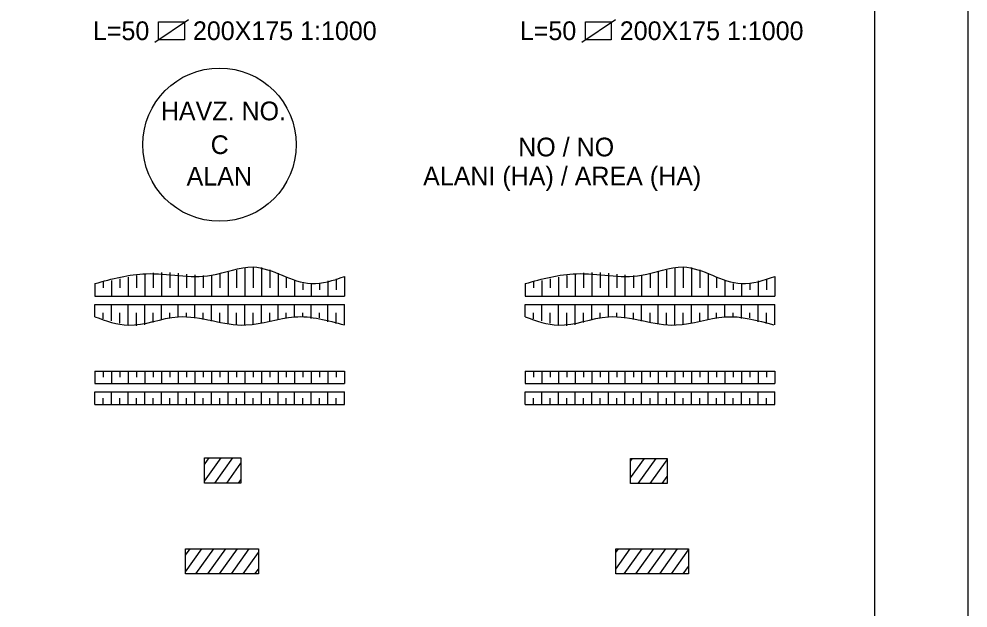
# Model space of a CAD drawing. Extents: x -10 to 1145, y -10 to 821.
# Drawn here: x 1043 to 1145, y 552.8 to 616.2 of the extents above; entities that cross this region are included whole.
import ezdxf

# ---------------------------------------------------------------- set-up
doc = ezdxf.new("R2010")
doc.units = 0
for name, color, linetype in [('Level 1', 7, 'Continuous'), ('Level 17', 7, 'Continuous'), ('Level 19', 7, 'Continuous'), ('Level 31', 7, 'Continuous'), ('Level 32', 7, 'Continuous'), ('Level 39', 7, 'Continuous'), ('Level 51', 7, 'Continuous'), ('Level 52', 7, 'Continuous')]:
    doc.layers.add(name, color=color, linetype=linetype)

msp = doc.modelspace()

# ---------------------------------------------------------------- linework, layer by layer
at = {"layer": 'Level 1'}
for p, q in [((1055.63, 588.62), (1055.63, 587.31)), ((1056.52, 588.79), (1056.52, 586.41)), ((1057.42, 588.92), (1057.42, 587.31)), ((1058.31, 588.96), (1058.31, 586.41)), ((1059.21, 588.93), (1059.21, 587.31)), ((1060.1, 588.87), (1060.1, 586.41)), ((1061, 588.78), (1061, 587.31)), ((1061.89, 588.7), (1061.89, 586.41)), ((1062.79, 588.64), (1062.79, 587.31)), ((1063.68, 588.65), (1063.68, 586.41)), ((1064.57, 588.76), (1064.57, 587.31)), ((1065.47, 588.98), (1065.47, 586.41)), ((1066.36, 589.21), (1066.36, 587.31)), ((1067.26, 589.43), (1067.26, 586.41)), ((1068.15, 589.54), (1068.15, 587.31)), ((1069.05, 589.47), (1069.05, 586.41)), ((1069.94, 589.23), (1069.94, 587.31)), ((1070.84, 588.87), (1070.84, 586.41)), ((1101.87, 588.62), (1101.87, 587.31)), ((1102.77, 588.79), (1102.77, 586.41)), ((1103.66, 588.92), (1103.66, 587.31)), ((1104.55, 588.96), (1104.55, 586.41)), ((1105.45, 588.93), (1105.45, 587.31)), ((1106.34, 588.87), (1106.34, 586.41)), ((1107.24, 588.78), (1107.24, 587.31)), ((1108.13, 588.7), (1108.13, 586.41)), ((1109.03, 588.64), (1109.03, 587.31)), ((1109.92, 588.65), (1109.92, 586.41)), ((1110.82, 588.76), (1110.82, 587.31)), ((1111.71, 588.98), (1111.71, 586.41)), ((1112.6, 589.21), (1112.6, 587.31)), ((1113.5, 589.43), (1113.5, 586.41)), ((1114.39, 589.54), (1114.39, 587.31)), ((1115.29, 589.47), (1115.29, 586.41)), ((1116.18, 589.23), (1116.18, 587.31)), ((1117.08, 588.87), (1117.08, 586.41)), ((1051.16, 587.75), (1051.16, 586.41)), ((1052.05, 587.93), (1052.05, 587.31)), ((1052.95, 588.1), (1052.95, 586.41)), ((1053.84, 588.27), (1053.84, 587.31)), ((1054.74, 588.44), (1054.74, 586.41)), ((1071.73, 588.49), (1071.73, 587.31)), ((1072.62, 588.12), (1072.62, 586.41)), ((1073.52, 587.75), (1073.52, 587.08)), ((1074.41, 587.75), (1074.41, 586.41)), ((1075.31, 587.75), (1075.31, 587.08)), ((1076.2, 588.04), (1076.2, 586.41)), ((1077.1, 588.28), (1077.1, 587.08)), ((1077.99, 588.51), (1077.99, 586.41)), ((1097.4, 587.75), (1097.4, 586.41)), ((1098.29, 587.93), (1098.29, 587.31)), ((1099.19, 588.1), (1099.19, 586.41)), ((1100.08, 588.27), (1100.08, 587.31)), ((1100.98, 588.44), (1100.98, 586.41)), ((1117.97, 588.49), (1117.97, 587.31)), ((1118.86, 588.12), (1118.86, 586.41)), ((1119.76, 587.75), (1119.76, 587.08)), ((1120.65, 587.75), (1120.65, 586.41)), ((1121.55, 587.75), (1121.55, 587.08)), ((1122.44, 588.04), (1122.44, 586.41)), ((1123.34, 588.28), (1123.34, 587.08)), ((1124.23, 588.51), (1124.23, 586.41)), ((1051.16, 586.41), (1077.99, 586.41)), ((1051.16, 585.52), (1077.99, 585.52)), ((1051.16, 584.18), (1051.16, 585.52)), ((1052.95, 583.73), (1052.95, 585.52)), ((1054.74, 583.28), (1054.74, 585.52)), ((1056.52, 583.33), (1056.52, 585.52)), ((1058.31, 583.85), (1058.31, 585.52)), ((1060.1, 584.18), (1060.1, 585.52)), ((1061.89, 584.03), (1061.89, 585.52)), ((1063.68, 583.72), (1063.68, 585.52)), ((1065.47, 583.43), (1065.47, 585.52)), ((1067.26, 583.3), (1067.26, 585.52)), ((1069.05, 583.53), (1069.05, 585.52)), ((1070.84, 583.93), (1070.84, 585.52)), ((1072.62, 584.18), (1072.62, 585.52)), ((1074.41, 584.01), (1074.41, 585.52)), ((1076.2, 583.64), (1076.2, 585.52)), ((1077.99, 583.31), (1077.99, 585.52)), ((1097.4, 586.41), (1124.23, 586.41)), ((1097.4, 585.52), (1124.23, 585.52)), ((1097.4, 584.18), (1097.4, 585.52)), ((1099.19, 583.73), (1099.19, 585.52)), ((1100.98, 583.28), (1100.98, 585.52)), ((1102.77, 583.33), (1102.77, 585.52)), ((1104.55, 583.85), (1104.55, 585.52)), ((1106.34, 584.18), (1106.34, 585.52)), ((1108.13, 584.03), (1108.13, 585.52)), ((1109.92, 583.72), (1109.92, 585.52)), ((1111.71, 583.43), (1111.71, 585.52)), ((1113.5, 583.3), (1113.5, 585.52)), ((1115.29, 583.53), (1115.29, 585.52)), ((1117.08, 583.93), (1117.08, 585.52)), ((1118.86, 584.18), (1118.86, 585.52)), ((1120.65, 584.01), (1120.65, 585.52)), ((1122.44, 583.64), (1122.44, 585.52)), ((1124.23, 583.31), (1124.23, 585.52)), ((1052.05, 583.95), (1052.05, 584.62)), ((1053.84, 583.5), (1053.84, 584.62)), ((1055.63, 583.2), (1055.63, 584.62)), ((1057.42, 583.57), (1057.42, 584.62)), ((1059.21, 584.08), (1059.21, 584.62)), ((1061, 584.18), (1061, 584.62)), ((1062.79, 583.88), (1062.79, 584.62)), ((1064.57, 583.57), (1064.57, 584.62)), ((1066.36, 583.33), (1066.36, 584.62)), ((1068.15, 583.36), (1068.15, 584.62)), ((1069.94, 583.73), (1069.94, 584.62)), ((1071.73, 583.99), (1071.73, 584.62)), ((1073.52, 584.14), (1073.52, 584.62)), ((1075.31, 584.06), (1075.31, 584.62)), ((1077.1, 583.45), (1077.1, 584.62)), ((1098.29, 583.95), (1098.29, 584.62)), ((1100.08, 583.51), (1100.08, 584.62)), ((1101.87, 583.2), (1101.87, 584.62)), ((1103.66, 583.57), (1103.66, 584.62)), ((1105.45, 584.08), (1105.45, 584.62)), ((1107.24, 584.18), (1107.24, 584.62)), ((1109.03, 583.88), (1109.03, 584.62)), ((1110.82, 583.57), (1110.82, 584.62)), ((1112.6, 583.33), (1112.6, 584.62)), ((1114.39, 583.36), (1114.39, 584.62)), ((1116.18, 583.73), (1116.18, 584.62)), ((1117.97, 583.99), (1117.97, 584.62)), ((1119.76, 584.14), (1119.76, 584.62)), ((1121.55, 584.06), (1121.55, 584.62)), ((1123.34, 583.45), (1123.34, 584.62)), ((1051.16, 578.34), (1077.99, 578.34)), ((1051.16, 578.34), (1051.16, 577)), ((1052.05, 578.34), (1052.05, 577.67)), ((1052.95, 578.34), (1052.95, 577)), ((1053.84, 578.34), (1053.84, 577.67)), ((1054.74, 578.34), (1054.74, 577)), ((1055.63, 578.34), (1055.63, 577.67)), ((1056.52, 578.34), (1056.52, 577)), ((1057.42, 578.34), (1057.42, 577.67)), ((1058.31, 578.34), (1058.31, 577)), ((1059.21, 578.34), (1059.21, 577.67)), ((1060.1, 578.34), (1060.1, 577)), ((1061, 578.34), (1061, 577.67)), ((1061.89, 578.34), (1061.89, 577)), ((1062.79, 578.34), (1062.79, 577.67)), ((1063.68, 578.34), (1063.68, 577)), ((1064.57, 578.34), (1064.57, 577.67)), ((1065.47, 578.34), (1065.47, 577)), ((1066.36, 578.34), (1066.36, 577.67)), ((1067.26, 578.34), (1067.26, 577)), ((1068.15, 578.34), (1068.15, 577.67)), ((1069.05, 578.34), (1069.05, 577)), ((1069.94, 578.34), (1069.94, 577.67)), ((1070.84, 578.34), (1070.84, 577)), ((1071.73, 578.34), (1071.73, 577.67)), ((1072.62, 578.34), (1072.62, 577)), ((1073.52, 578.34), (1073.52, 577.67)), ((1074.41, 578.34), (1074.41, 577)), ((1075.31, 578.34), (1075.31, 577.67)), ((1076.2, 578.34), (1076.2, 577)), ((1077.1, 578.34), (1077.1, 577.67)), ((1077.99, 578.34), (1077.99, 577)), ((1097.4, 578.34), (1124.23, 578.34)), ((1097.4, 578.34), (1097.4, 577)), ((1098.29, 578.34), (1098.29, 577.67)), ((1099.19, 578.34), (1099.19, 577)), ((1100.08, 578.34), (1100.08, 577.67)), ((1100.98, 578.34), (1100.98, 577)), ((1101.87, 578.34), (1101.87, 577.67)), ((1102.77, 578.34), (1102.77, 577)), ((1103.66, 578.34), (1103.66, 577.67)), ((1104.55, 578.34), (1104.55, 577)), ((1105.45, 578.34), (1105.45, 577.67)), ((1106.34, 578.34), (1106.34, 577)), ((1107.24, 578.34), (1107.24, 577.67)), ((1108.13, 578.34), (1108.13, 577)), ((1109.03, 578.34), (1109.03, 577.67)), ((1109.92, 578.34), (1109.92, 577)), ((1110.82, 578.34), (1110.82, 577.67)), ((1111.71, 578.34), (1111.71, 577)), ((1112.6, 578.34), (1112.6, 577.67)), ((1113.5, 578.34), (1113.5, 577)), ((1114.39, 578.34), (1114.39, 577.67)), ((1115.29, 578.34), (1115.29, 577)), ((1116.18, 578.34), (1116.18, 577.67)), ((1117.08, 578.34), (1117.08, 577)), ((1117.97, 578.34), (1117.97, 577.67)), ((1118.86, 578.34), (1118.86, 577)), ((1119.76, 578.34), (1119.76, 577.67)), ((1120.65, 578.34), (1120.65, 577)), ((1121.55, 578.34), (1121.55, 577.67)), ((1122.44, 578.34), (1122.44, 577)), ((1123.34, 578.34), (1123.34, 577.67)), ((1124.23, 578.34), (1124.23, 577)), ((1051.16, 577), (1077.99, 577)), ((1097.4, 577), (1124.23, 577)), ((1051.16, 576.1), (1077.99, 576.1)), ((1051.16, 574.76), (1051.16, 576.1)), ((1052.05, 574.76), (1052.05, 575.43)), ((1052.95, 574.76), (1052.95, 576.1)), ((1053.84, 574.76), (1053.84, 575.43)), ((1054.74, 574.76), (1054.74, 576.1)), ((1055.63, 574.76), (1055.63, 575.43)), ((1056.52, 574.76), (1056.52, 576.1)), ((1057.42, 574.76), (1057.42, 575.43)), ((1058.31, 574.76), (1058.31, 576.1)), ((1059.21, 574.76), (1059.21, 575.43)), ((1060.1, 574.76), (1060.1, 576.1)), ((1061, 574.76), (1061, 575.43)), ((1061.89, 574.76), (1061.89, 576.1)), ((1062.79, 574.76), (1062.79, 575.43)), ((1063.68, 574.76), (1063.68, 576.1)), ((1064.57, 574.76), (1064.57, 575.43)), ((1065.47, 574.76), (1065.47, 576.1)), ((1066.36, 574.76), (1066.36, 575.43)), ((1067.26, 574.76), (1067.26, 576.1)), ((1068.15, 574.76), (1068.15, 575.43)), ((1069.05, 574.76), (1069.05, 576.1)), ((1069.94, 574.76), (1069.94, 575.43)), ((1070.84, 574.76), (1070.84, 576.1)), ((1071.73, 574.76), (1071.73, 575.43)), ((1072.62, 574.76), (1072.62, 576.1)), ((1073.52, 574.76), (1073.52, 575.43)), ((1074.41, 574.76), (1074.41, 576.1)), ((1075.31, 574.76), (1075.31, 575.43)), ((1076.2, 574.76), (1076.2, 576.1)), ((1077.1, 574.76), (1077.1, 575.43)), ((1077.99, 574.76), (1077.99, 576.1)), ((1097.4, 576.1), (1124.23, 576.1)), ((1097.4, 574.76), (1097.4, 576.1)), ((1098.29, 574.76), (1098.29, 575.43)), ((1099.19, 574.76), (1099.19, 576.1)), ((1100.08, 574.76), (1100.08, 575.43)), ((1100.98, 574.76), (1100.98, 576.1)), ((1101.87, 574.76), (1101.87, 575.43)), ((1102.77, 574.76), (1102.77, 576.1)), ((1103.66, 574.76), (1103.66, 575.43)), ((1104.55, 574.76), (1104.55, 576.1)), ((1105.45, 574.76), (1105.45, 575.43)), ((1106.34, 574.76), (1106.34, 576.1)), ((1107.24, 574.76), (1107.24, 575.43)), ((1108.13, 574.76), (1108.13, 576.1)), ((1109.03, 574.76), (1109.03, 575.43)), ((1109.92, 574.76), (1109.92, 576.1)), ((1110.82, 574.76), (1110.82, 575.43)), ((1111.71, 574.76), (1111.71, 576.1)), ((1112.6, 574.76), (1112.6, 575.43)), ((1113.5, 574.76), (1113.5, 576.1)), ((1114.39, 574.76), (1114.39, 575.43)), ((1115.29, 574.76), (1115.29, 576.1)), ((1116.18, 574.76), (1116.18, 575.43)), ((1117.08, 574.76), (1117.08, 576.1)), ((1117.97, 574.76), (1117.97, 575.43)), ((1118.86, 574.76), (1118.86, 576.1)), ((1119.76, 574.76), (1119.76, 575.43)), ((1120.65, 574.76), (1120.65, 576.1)), ((1121.55, 574.76), (1121.55, 575.43)), ((1122.44, 574.76), (1122.44, 576.1)), ((1123.34, 574.76), (1123.34, 575.43)), ((1124.23, 574.76), (1124.23, 576.1)), ((1051.16, 574.76), (1077.99, 574.76)), ((1097.4, 574.76), (1124.23, 574.76))]:
    msp.add_line(p, q, dxfattribs=at)
for points in [[(1051.16, 587.75), (1056.67, 588.82), (1063.68, 588.65), (1068.15, 589.54), (1074.41, 587.75), (1077.97, 588.51)], [(1097.4, 587.75), (1102.91, 588.82), (1109.92, 588.65), (1114.39, 589.54), (1120.65, 587.75), (1124.23, 588.52)], [(1051.16, 584.18), (1054.74, 583.28), (1060.1, 584.18), (1067.39, 583.3), (1072.62, 584.18), (1077.97, 583.3)], [(1097.4, 584.18), (1100.98, 583.28), (1106.34, 584.18), (1113.63, 583.3), (1118.86, 584.18), (1124.13, 583.31)]]:
    msp.add_spline(points, degree=3, dxfattribs=at)
at = {"layer": 'Level 17'}
for p, q in [((1057.61, 613.74), (1061.21, 616.16)), ((1057.61, 613.74), (1061.21, 616.16)), ((1103.5, 613.74), (1107.1, 616.16)), ((1103.5, 613.74), (1107.1, 616.16)), ((1057.99, 615.91), (1060.82, 615.91)), ((1103.88, 615.91), (1106.71, 615.91))]:
    msp.add_line(p, q, dxfattribs=at)
for points in [[(1057.99, 615.9), (1060.77, 615.9), (1060.77, 613.98), (1057.99, 613.98)], [(1103.88, 615.9), (1106.66, 615.9), (1106.66, 613.98), (1103.88, 613.98)]]:
    msp.add_lwpolyline(points, close=True, dxfattribs=at)
at = {"layer": 'Level 19'}
for p, q in [((1062.93, 566.5), (1064.71, 569.01)), ((1062.93, 568.29), (1063.44, 569.01)), ((1062.93, 566.3), (1062.93, 569.01)), ((1064.06, 566.3), (1065.99, 569.01)), ((1065.33, 566.3), (1066.85, 568.43)), ((1108.74, 566.86), (1110.22, 568.94)), ((1108.74, 568.65), (1108.95, 568.94)), ((1108.74, 566.23), (1108.74, 568.94)), ((1109.56, 566.23), (1111.49, 568.94)), ((1110.84, 566.23), (1112.66, 568.79)), ((1066.6, 566.3), (1066.85, 566.64)), ((1112.11, 566.23), (1112.66, 567.01)), ((1060.9, 558.54), (1061.39, 559.22)), ((1060.9, 556.75), (1062.66, 559.22)), ((1060.9, 556.52), (1060.9, 559.22)), ((1062.01, 556.52), (1063.93, 559.22)), ((1063.28, 556.52), (1065.21, 559.22)), ((1064.55, 556.52), (1066.48, 559.22)), ((1065.82, 556.52), (1067.75, 559.22)), ((1107.13, 557.02), (1108.7, 559.22)), ((1107.14, 558.82), (1107.43, 559.22)), ((1107.14, 556.52), (1107.14, 559.22)), ((1108.04, 556.52), (1109.97, 559.22)), ((1109.31, 556.52), (1111.24, 559.22)), ((1110.58, 556.52), (1112.51, 559.22)), ((1111.86, 556.52), (1113.78, 559.22)), ((1113.13, 556.52), (1114.97, 559.11)), ((1067.09, 556.52), (1068.73, 558.82)), ((1068.36, 556.52), (1068.73, 557.04)), ((1114.4, 556.52), (1114.97, 557.32))]:
    msp.add_line(p, q, dxfattribs=at)
for points in [[(1062.93, 569.01), (1066.85, 569.01), (1066.85, 566.3), (1062.93, 566.3)], [(1108.74, 568.94), (1112.66, 568.94), (1112.66, 566.23), (1108.74, 566.23)], [(1107.14, 559.22), (1114.97, 559.22), (1114.97, 556.52), (1107.14, 556.52)]]:
    msp.add_lwpolyline(points, close=True, dxfattribs=at)
for points in [[(1064.82, 556.52), (1060.9, 556.52), (1060.9, 559.22), (1064.82, 559.22)], [(1064.82, 559.22), (1068.73, 559.22), (1068.73, 556.52), (1064.82, 556.52)]]:
    msp.add_lwpolyline(points, dxfattribs=at)
at = {"layer": 'Level 31'}
msp.add_circle((1064.55, 602.7), 8.24, dxfattribs=at)
at = {"layer": 'Level 51'}
msp.add_lwpolyline([(-10, -10), (1145, -10), (1145, 821), (-10, 821)], close=True, dxfattribs=at)
at = {"layer": 'Level 52'}
msp.add_lwpolyline([(965, 287), (1135, 287), (1135, 811), (965, 811)], close=True, dxfattribs=at)

# ---------------------------------------------------------------- texts
at = {"layer": 'Level 17'}
for s, height, p in [('L=50', 2.012, (1050.94, 613.95)), ('200X175 1:1000', 2.0119, (1061.69, 613.95)), ('L=50', 2.012, (1096.83, 613.95)), ('200X175 1:1000', 2.0119, (1107.57, 613.95))]:
    msp.add_text(s, height=height, rotation=359.987, dxfattribs=at).set_placement(p)
at = {"layer": 'Level 32'}
for s, height, p in [('HAVZ. NO.', 2.012, (1058.24, 605.32)), ('C', 2.01, (1063.6, 601.69)), ('ALAN', 2.012, (1061.01, 598.3))]:
    msp.add_text(s, height=height, rotation=360, dxfattribs=at).set_placement(p)
at = {"layer": 'Level 39'}
for s, height, p in [('NO / NO', 2.012, (1096.65, 601.44)), ('ALANI (HA) / AREA (HA)', 2.0119, (1086.43, 598.31))]:
    msp.add_text(s, height=height, rotation=360, dxfattribs=at).set_placement(p)

doc.saveas('drawing.dxf')
